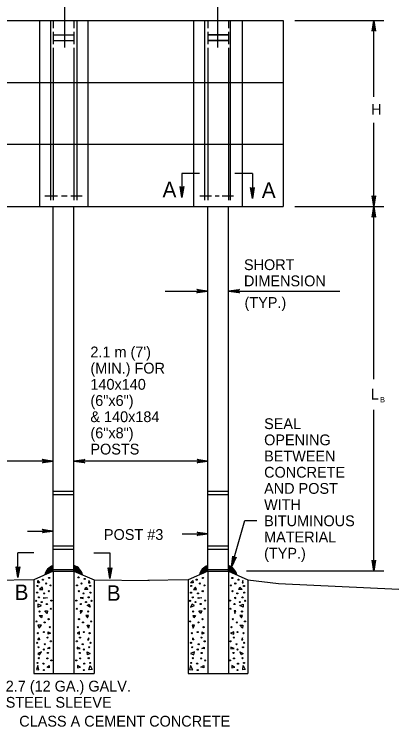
# Model space of a CAD drawing. Extents: x -1958 to 628, y -879 to 309.
# Drawn here: x 246.6 to 353.5, y 4.9 to 203 of the extents above; entities that cross this region are included whole.
import ezdxf

# ---------------------------------------------------------------- set-up
doc = ezdxf.new("R2010")
doc.units = 0
for name, color, linetype in [('2', 7, 'Continuous'), ('3', 7, 'Continuous'), ('4', 7, 'Continuous')]:
    doc.layers.add(name, color=color, linetype=linetype)

# ---------------------------------------------------------------- blocks, each defined once
blk = doc.blocks.new('RARROW')
at = {"layer": '3'}
blk.add_lwpolyline([(-0.0576, 0.0072), (-0.0555, 0.0031), (0, 0), (-0.0576, 0.0072), (-0.0606, 0.0098), (0, 0), (-0.0555, -0.0027), (-0.0575, -0.0069), (0, 0), (-0.0606, -0.0096), (-0.0575, -0.0069)], dxfattribs=at)

msp = doc.modelspace()

# ---------------------------------------------------------------- linework, layer by layer
at = {"layer": '2'}
for p, q in [((199.49, 201.26), (321.32, 201.26)), ((253.6, 201.26), (253.6, 149.52)), ((256.67, 201.26), (256.67, 151.25)), ((257.45, 201.26), (257.45, 199.13)), ((263.2, 201.26), (263.2, 199.13)), ((263.99, 201.26), (263.99, 151.25)), ((267.06, 201.26), (267.06, 149.52)), ((296.44, 201.26), (296.44, 149.52)), ((299.51, 201.26), (299.51, 151.25)), ((300.45, 201.26), (300.45, 199.13)), ((306.12, 201.26), (306.12, 199.13)), ((306.59, 201.26), (306.59, 151.25)), ((309.98, 201.26), (309.98, 149.52)), ((321.32, 201.26), (321.32, 149.52)), ((257.45, 198.03), (257.45, 194.65)), ((263.2, 198.03), (263.2, 194.65)), ((300.45, 198.03), (300.45, 194.65)), ((306.12, 198.03), (306.12, 194.65)), ((257.45, 197.24), (263.2, 197.24)), ((300.45, 197.24), (306.12, 197.24)), ((306.12, 197.24), (300.45, 197.24)), ((257.45, 195.67), (263.2, 195.67)), ((300.45, 195.67), (306.12, 195.67)), ((306.12, 195.67), (300.45, 195.67)), ((257.45, 193.62), (257.45, 151.25)), ((263.2, 193.62), (263.2, 151.25)), ((300.45, 193.62), (300.45, 151.25)), ((306.12, 193.62), (306.12, 151.25)), ((199.49, 184.01), (321.32, 184.01)), ((199.49, 166.85), (321.32, 166.85)), ((199.49, 149.52), (321.32, 149.52)), ((257.45, 48.2), (257.45, 149.52)), ((263.2, 48.2), (263.2, 149.52)), ((300.45, 48.2), (300.45, 149.52)), ((306.12, 48.2), (306.12, 149.52)), ((257.45, 70.41), (263.21, 70.41)), ((257.45, 69.47), (263.21, 69.47)), ((300.32, 70.41), (306.22, 70.41)), ((300.32, 70.41), (305.99, 70.41)), ((300.32, 69.47), (306.22, 69.47)), ((300.32, 69.47), (305.99, 69.47)), ((257.45, 55.21), (263.21, 55.21)), ((257.45, 54.27), (263.21, 54.27)), ((300.45, 55.21), (306.12, 55.21)), ((300.45, 54.27), (306.12, 54.27)), ((257.45, 48.2), (252.02, 45.76)), ((257.45, 48.68), (263.2, 48.68)), ((257.45, 48.2), (263.2, 48.2)), ((257.45, 48.2), (257.45, 19.7)), ((263.2, 48.2), (268.79, 45.76)), ((263.2, 48.2), (263.2, 19.7)), ((300.45, 48.2), (294.94, 45.76)), ((300.45, 48.68), (306.12, 48.68)), ((300.45, 48.2), (306.12, 48.2)), ((300.45, 48.2), (300.45, 19.7)), ((306.12, 48.2), (311.56, 45.76)), ((306.12, 48.2), (306.12, 19.7)), ((252.02, 45.76), (252.02, 19.7)), ((268.79, 45.76), (268.79, 19.7)), ((294.94, 45.76), (294.94, 19.7)), ((311.56, 45.76), (311.56, 19.7)), ((252.02, 19.7), (268.79, 19.7)), ((294.94, 19.7), (311.56, 19.7))]:
    msp.add_line(p, q, dxfattribs=at)
for points in [[(252.02, 45.76), (240.92, 45.6)], [(268.79, 45.76), (284.07, 45.6)], [(294.94, 45.76), (283.76, 45.6)], [(311.56, 45.76), (320.02, 44.72), (353.48, 43.14)]]:
    msp.add_lwpolyline(points, dxfattribs=at)
for points in [[(253.6, 44.9), (253.12, 44.9), (253.2, 45.6)], [(267.22, 44.9), (267.69, 44.9), (267.38, 45.6)], [(296.36, 44.9), (295.57, 44.9), (296.2, 45.6)], [(309.98, 44.9), (310.22, 44.9), (310.14, 45.6)], [(253.6, 43.08), (254.54, 43.08), (254.38, 43.71)], [(267.06, 43.08), (266.27, 43.08), (266.51, 43.71)], [(296.44, 43.08), (297.3, 43.08), (296.99, 43.71)], [(309.98, 43.08), (309.04, 43.08), (309.27, 43.71)], [(254.86, 40.56), (254.86, 40.88), (255.88, 40.72)], [(265.72, 40.56), (265.72, 40.88), (264.94, 40.72)], [(297.77, 40.56), (297.77, 40.88), (298.72, 40.72)], [(308.17, 40.56), (308.17, 40.88), (307.7, 40.72)], [(253.12, 38.99), (253.12, 38.2), (254.15, 38.67)], [(267.46, 38.99), (267.69, 38.2), (266.9, 38.67)], [(296.04, 38.99), (295.57, 38.2), (296.67, 38.67)], [(310.22, 38.99), (310.22, 38.2), (309.35, 38.67)], [(253.52, 35.84), (254.38, 35.84), (254.15, 35.21)], [(255.09, 37.18), (255.88, 37.18), (255.72, 36.39)], [(265.57, 37.18), (264.94, 37.18), (265.01, 36.39)], [(267.22, 35.84), (266.51, 35.84), (266.98, 35.21)], [(296.36, 35.84), (296.99, 35.84), (296.51, 35.21)], [(297.93, 37.18), (298.72, 37.18), (298.48, 36.39)], [(308.17, 37.18), (307.7, 37.18), (307.93, 36.39)], [(310.06, 35.84), (309.27, 35.84), (309.74, 35.21)], [(254.15, 33.16), (253.2, 33.16), (253.52, 32.3)], [(266.9, 33.16), (267.46, 33.16), (267.22, 32.3)], [(296.67, 33.16), (296.04, 33.16), (296.36, 32.3)], [(309.35, 33.16), (310.14, 33.16), (310.06, 32.3)], [(256.04, 30.64), (256.04, 31.35), (256.67, 30.96)], [(264.7, 30.64), (264.7, 31.35), (264.07, 30.96)], [(298.8, 30.64), (298.8, 31.35), (299.43, 30.96)], [(307.62, 30.64), (307.62, 31.35), (306.75, 30.96)], [(253.67, 29.07), (253.2, 29.07), (253.52, 29.62)], [(266.98, 29.07), (267.38, 29.07), (267.3, 29.62)], [(296.51, 29.07), (296.2, 29.07), (296.28, 29.62)], [(309.74, 29.07), (310.14, 29.07), (310.06, 29.62)], [(253.67, 24.97), (254.15, 25.76), (253.12, 25.29)], [(256.43, 27.02), (256.43, 26.63), (255.88, 26.7)], [(264.07, 27.02), (264.07, 26.63), (264.94, 26.7)], [(266.98, 24.97), (266.9, 25.76), (267.69, 25.29)], [(296.51, 24.97), (296.67, 25.76), (295.57, 25.29)], [(299.35, 27.02), (299.35, 26.63), (298.72, 26.7)], [(306.83, 27.02), (306.83, 26.63), (307.7, 26.7)], [(309.74, 24.97), (309.35, 25.76), (310.22, 25.29)], [(252.81, 20.88), (253.44, 20.8), (253.12, 21.98)], [(256.35, 21.98), (256.35, 21.35), (255.72, 21.51)], [(264.23, 21.98), (264.23, 21.35), (265.01, 21.51)], [(268.24, 20.88), (267.3, 20.8), (267.69, 21.98)], [(295.33, 20.88), (296.28, 20.8), (295.57, 21.98)], [(299.27, 21.98), (299.27, 21.35), (298.48, 21.51)], [(307.07, 21.98), (307.07, 21.35), (307.93, 21.51)], [(310.77, 20.88), (310.14, 20.8), (310.22, 21.98)]]:
    msp.add_lwpolyline(points, close=True, dxfattribs=at)
for centre, major_axis, start_param, end_param in [((258.64, 46.67), (-3.59, 0), 5.049782, 6.134444), ((258.64, 46.67), (-3.48, 0), 5.061257, 6.112974), ((261.99, 46.72), (3.48, 0), 0.164297, 1.213759), ((261.99, 46.72), (3.59, 0), 0.143581, 1.218869), ((261.99, 46.72), (3.35, 0), 0.193006, 1.190655), ((301.63, 46.68), (-3.59, 0), 5.048279, 6.134323), ((301.63, 46.68), (-3.48, 0), 5.058902, 6.113111), ((304.89, 46.69), (3.59, 0), 0.146911, 1.218869), ((304.89, 46.69), (3.48, 0), 0.168297, 1.204055), ((258.64, 46.67), (-3.35, 0), 5.075898, 6.083179), ((258.64, 46.67), (-3.18, 0), 5.095864, 6.041663), ((258.64, 46.67), (-3.03, 0), 5.116244, 5.998084), ((258.64, 46.67), (-2.87, 0), 5.140569, 5.94416), ((258.64, 46.67), (-2.69, 0), 5.185431, 5.865794), ((258.64, 46.67), (-2.52, 0), 5.215878, 5.780715), ((258.64, 46.67), (-2.35, 0), 5.263543, 5.680676), ((258.64, 46.67), (-2.17, 0), 5.317304, 5.495478), ((261.99, 46.72), (2.52, 0), 0.502471, 1.067308), ((261.99, 46.72), (2.69, 0), 0.391681, 1.097754), ((261.99, 46.72), (3.18, 0), 0.232926, 1.171279), ((261.99, 46.72), (3.03, 0), 0.274712, 1.150118), ((261.99, 46.72), (2.87, 0), 0.326219, 1.124043), ((261.99, 46.72), (2.35, 0), 0.60251, 1.019643), ((261.99, 46.72), (2.17, 0), 0.745101, 0.965881), ((301.63, 46.68), (-3.35, 0), 5.073435, 6.083689), ((301.63, 46.68), (-3.18, 0), 5.093253, 6.042722), ((301.63, 46.68), (-3.03, 0), 5.113478, 5.999761), ((301.63, 46.68), (-2.87, 0), 5.137615, 5.946674), ((301.63, 46.68), (-2.69, 0), 5.166915, 5.878941), ((301.63, 46.68), (-2.52, 0), 5.201449, 5.780715), ((301.63, 46.68), (-2.35, 0), 5.238657, 5.680676), ((301.63, 46.68), (-2.17, 0), 5.288522, 5.513079), ((304.89, 46.69), (2.52, 0), 0.502471, 1.067308), ((304.89, 46.69), (2.69, 0), 0.417391, 1.097754), ((304.89, 46.69), (3.35, 0), 0.197969, 1.190655), ((304.89, 46.69), (3.18, 0), 0.239305, 1.171279), ((304.89, 46.69), (3.03, 0), 0.282682, 1.150118), ((304.89, 46.69), (2.87, 0), 0.336331, 1.124043), ((304.89, 46.69), (2.35, 0), 0.60251, 1.019643), ((304.89, 46.69), (2.17, 0), 0.779924, 0.965881)]:
    msp.add_ellipse(centre, major_axis=major_axis, ratio=0.9, start_param=start_param, end_param=end_param, dxfattribs=at)
for centre, major_axis, ratio in [((254.57, 45.8), (0.154, 0), 0.99999), ((256.3, 46.28), (0.154, 0), 0.99999), ((264.47, 46.46), (-0.154, 0), 0.9), ((266.19, 46.03), (-0.154, 0), 0.9), ((297.32, 45.8), (0.154, 0), 0.99999), ((299.04, 46.28), (0.154, 0), 0.99999), ((307.22, 46.28), (-0.154, 0), 0.99999), ((308.94, 45.8), (-0.154, 0), 0.99999), ((253.05, 44.07), (0.154, 0), 0.99999), ((255.47, 44.76), (0.154, 0), 0.99999), ((256.71, 44.21), (0.154, 0), 0.99999), ((264.06, 44.21), (-0.154, 0), 0.99999), ((265.3, 44.76), (-0.154, 0), 0.99999), ((267.71, 44.07), (-0.154, 0), 0.99999), ((295.8, 44.07), (0.154, 0), 0.99999), ((298.22, 44.76), (0.154, 0), 0.99999), ((299.46, 44.21), (0.154, 0), 0.99999), ((306.81, 44.21), (-0.154, 0), 0.99999), ((308.05, 44.76), (-0.154, 0), 0.99999), ((310.46, 44.07), (-0.154, 0), 0.99999), ((252.99, 42.21), (0.154, 0), 0.99999), ((254.92, 42), (0.154, 0), 0.99999), ((256.23, 42.62), (0.154, 0), 0.99999), ((264.54, 42.62), (-0.154, 0), 0.99999), ((265.85, 42), (-0.154, 0), 0.99999), ((267.78, 42.21), (-0.154, 0), 0.99999), ((295.73, 42.21), (0.154, 0), 0.99999), ((297.67, 42), (0.154, 0), 0.99999), ((298.98, 42.62), (0.154, 0), 0.99999), ((307.29, 42.62), (-0.154, 0), 0.99999), ((308.6, 42), (-0.154, 0), 0.99999), ((310.53, 42.21), (-0.154, 0), 0.99999), ((252.71, 39.93), (0.154, 0), 0.99999), ((253.47, 40.9), (0.154, 0), 0.99999), ((254.23, 39.59), (0.154, 0), 0.99999), ((256.92, 40), (0.154, 0), 0.99999), ((263.85, 40), (-0.154, 0), 0.99999), ((266.54, 39.59), (-0.154, 0), 0.99999), ((267.3, 40.9), (-0.154, 0), 0.99999), ((268.06, 39.93), (-0.154, 0), 0.99999), ((295.46, 39.93), (0.154, 0), 0.99999), ((296.22, 40.9), (0.154, 0), 0.99999), ((296.98, 39.59), (0.154, 0), 0.99999), ((299.67, 40), (0.154, 0), 0.99999), ((306.6, 40), (-0.154, 0), 0.99999), ((309.29, 39.59), (-0.154, 0), 0.99999), ((310.05, 40.9), (-0.154, 0), 0.99999), ((310.81, 39.93), (-0.154, 0), 0.99999), ((255.67, 39.04), (0.154, 0), 0.99999), ((256.78, 37.73), (0.154, 0), 0.99999), ((263.99, 37.73), (-0.154, 0), 0.99999), ((265.09, 39.04), (-0.154, 0), 0.99999), ((298.42, 39.04), (0.154, 0), 0.99999), ((299.53, 37.73), (0.154, 0), 0.99999), ((306.74, 37.73), (-0.154, 0), 0.99999), ((307.84, 39.04), (-0.154, 0), 0.99999), ((253.61, 36.97), (0.154, 0), 0.99999), ((267.16, 36.97), (-0.154, 0), 0.99999), ((296.36, 36.97), (0.154, 0), 0.99999), ((309.91, 36.97), (-0.154, 0), 0.99999), ((252.78, 34.21), (0.154, 0), 0.99999), ((255.05, 33.93), (0.154, 0), 0.99999), ((256.16, 34.83), (0.154, 0), 0.99999), ((264.61, 34.83), (-0.154, 0), 0.99999), ((265.71, 33.93), (-0.154, 0), 0.99999), ((267.99, 34.21), (-0.154, 0), 0.99999), ((295.53, 34.21), (0.154, 0), 0.99999), ((297.8, 33.93), (0.154, 0), 0.99999), ((298.91, 34.83), (0.154, 0), 0.99999), ((307.36, 34.83), (-0.154, 0), 0.99999), ((308.46, 33.93), (-0.154, 0), 0.99999), ((310.74, 34.21), (-0.154, 0), 0.99999), ((256.5, 32.62), (0.154, 0), 0.99999), ((264.26, 32.62), (-0.154, 0), 0.99999), ((299.25, 32.62), (0.154, 0), 0.99999), ((307.01, 32.62), (-0.154, 0), 0.99999), ((253.19, 30.96), (0.154, 0), 0.99999), ((254.85, 31.24), (0.154, 0), 0.99999), ((255.88, 29.72), (0.154, 0), 0.99999), ((264.88, 29.72), (-0.154, 0), 0.99999), ((265.92, 31.24), (-0.154, 0), 0.99999), ((267.57, 30.96), (-0.154, 0), 0.99999), ((295.94, 30.96), (0.154, 0), 0.99999), ((297.6, 31.24), (0.154, 0), 0.99999), ((298.63, 29.72), (0.154, 0), 0.99999), ((307.63, 29.72), (-0.154, 0), 0.99999), ((308.67, 31.24), (-0.154, 0), 0.99999), ((310.32, 30.96), (-0.154, 0), 0.99999), ((252.99, 28.27), (0.154, 0), 0.99999), ((255.12, 27.86), (0.154, 0), 0.99999), ((256.78, 28.69), (0.154, 0), 0.99999), ((263.99, 28.69), (-0.154, 0), 0.99999), ((265.64, 27.86), (-0.154, 0), 0.99999), ((267.78, 28.27), (-0.154, 0), 0.99999), ((295.73, 28.27), (0.154, 0), 0.99999), ((297.87, 27.86), (0.154, 0), 0.99999), ((299.53, 28.69), (0.154, 0), 0.99999), ((306.74, 28.69), (-0.154, 0), 0.99999), ((308.39, 27.86), (-0.154, 0), 0.99999), ((310.53, 28.27), (-0.154, 0), 0.99999), ((253.33, 27.03), (0.154, 0), 0.99999), ((254.85, 26.41), (0.154, 0), 0.99999), ((265.92, 26.41), (-0.154, 0), 0.99999), ((267.44, 27.03), (-0.154, 0), 0.99999), ((296.08, 27.03), (0.154, 0), 0.99999), ((297.6, 26.41), (0.154, 0), 0.99999), ((308.67, 26.41), (-0.154, 0), 0.99999), ((310.18, 27.03), (-0.154, 0), 0.99999), ((253.47, 23.99), (0.154, 0), 0.99999), ((255.81, 23.93), (0.154, 0), 0.99999), ((255.95, 25.44), (0.154, 0), 0.99999), ((264.82, 25.44), (-0.154, 0), 0.99999), ((264.95, 23.93), (-0.154, 0), 0.99999), ((267.3, 23.99), (-0.154, 0), 0.99999), ((296.22, 23.99), (0.154, 0), 0.99999), ((298.56, 23.93), (0.154, 0), 0.99999), ((298.7, 25.44), (0.154, 0), 0.99999), ((307.56, 25.44), (-0.154, 0), 0.99999), ((307.7, 23.93), (-0.154, 0), 0.99999), ((310.05, 23.99), (-0.154, 0), 0.99999), ((253.05, 22.68), (0.154, 0), 0.99999), ((254.71, 22.48), (0.154, 0), 0.99999), ((256.92, 23.37), (0.154, 0), 0.99999), ((263.85, 23.37), (-0.154, 0), 0.99999), ((266.06, 22.48), (-0.154, 0), 0.99999), ((267.71, 22.68), (-0.154, 0), 0.99999), ((295.8, 22.68), (0.154, 0), 0.99999), ((297.46, 22.48), (0.154, 0), 0.99999), ((299.67, 23.37), (0.154, 0), 0.99999), ((306.6, 23.37), (-0.154, 0), 0.99999), ((308.81, 22.48), (-0.154, 0), 0.99999), ((310.46, 22.68), (-0.154, 0), 0.99999), ((254.85, 20.68), (0.154, 0), 0.99999), ((265.92, 20.68), (-0.154, 0), 0.99999), ((297.6, 20.68), (0.154, 0), 0.99999), ((308.67, 20.68), (-0.154, 0), 0.99999)]:
    msp.add_ellipse(centre, major_axis=major_axis, ratio=ratio, dxfattribs=at)
at = {"layer": '3'}
for p, q in [((260.53, 209.77), (260.53, 193.7)), ((303.13, 209.77), (303.13, 193.7)), ((324.63, 201.26), (349.31, 201.26)), ((346.55, 180.01), (346.55, 201.26)), ((346.55, 149.52), (346.55, 172.75)), ((293.2, 158.67), (293.2, 152.07)), ((298.08, 158.67), (293.2, 158.67)), ((312.81, 158.67), (307.93, 158.67)), ((312.81, 158.67), (312.81, 151.77)), ((258.63, 152.37), (255.12, 152.37)), ((261.32, 152.37), (259.76, 152.37)), ((265.51, 152.37), (262.32, 152.37)), ((301.47, 152.37), (298.15, 152.37)), ((303.6, 152.37), (302.41, 152.37)), ((307.53, 152.37), (304.42, 152.37)), ((324.63, 149.52), (349.31, 149.52)), ((346.55, 101.57), (346.55, 149.52)), ((288.54, 126), (300.38, 126)), ((306.2, 126), (337.14, 126)), ((346.55, 48.2), (346.55, 93.04)), ((257.45, 78.76), (220.6, 78.76)), ((300.45, 78.76), (263.2, 78.76)), ((250.26, 59.33), (257.45, 59.33)), ((293.29, 58.54), (300.45, 58.54)), ((247.61, 46.4), (247.61, 53.28)), ((252.02, 53.24), (247.61, 53.24)), ((268.72, 53.24), (273.2, 53.24)), ((273.2, 53.24), (273.2, 46.12)), ((349.31, 48.2), (311.16, 48.2))]:
    msp.add_line(p, q, dxfattribs=at)
msp.add_lwpolyline([(307.01, 49.29), (310.68, 62.26), (314.04, 62.26)], dxfattribs=at)

# ---------------------------------------------------------------- block references
at = {"layer": '2'}
for p, xscale, yscale, rotation in [((346.55, 201.26), 49.50530586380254, 51.54709073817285, 89.99999999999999), ((293.2, 152.07), 49.50530586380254, 51.54709073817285, -90.00000000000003), ((312.81, 151.77), 49.50530586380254, 51.54709073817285, -90.00000000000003), ((346.55, 149.52), 49.50530586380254, 51.54709073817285, -90.00000000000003), ((346.55, 149.52), 49.50530586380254, 51.54709073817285, 89.99999999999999), ((306.2, 126), 49.50530586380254, 51.54709073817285, 180), ((263.2, 78.76), 49.50530586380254, 51.54709073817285, 180), ((307.01, 49.29), 49.50530586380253, 51.547090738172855, -105.57754519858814), ((346.55, 48.2), 49.50530586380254, 51.54709073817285, -90.00000000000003), ((247.61, 46.4), 49.50530586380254, 51.54709073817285, -90.00000000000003), ((273.2, 46.12), 49.50530586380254, 51.54709073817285, -90.00000000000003)]:
    msp.add_blockref('RARROW', p, dxfattribs=dict(at, xscale=xscale, yscale=yscale, rotation=rotation))
at = {"layer": '2', "xscale": 49.50530586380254, "yscale": 51.54709073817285}
for p in [(300.38, 126), (257.45, 78.76), (300.45, 78.76), (257.45, 59.33), (300.45, 58.54)]:
    msp.add_blockref('RARROW', p, dxfattribs=at)

# ---------------------------------------------------------------- texts
at = {"layer": '2'}
for s, p in [("2.1 m (7')", (267.78, 107.6)), ('(MIN.) FOR', (267.78, 103.1)), ('140x140 ', (267.78, 98.6)), ('(6"x6") ', (267.78, 94.1)), ('& 140x184', (267.78, 89.6)), ('(6"x8") ', (267.78, 85.1)), ('POSTS', (267.78, 80.6))]:
    msp.add_text(s, height=3, dxfattribs=at).set_placement(p)
at = {"layer": '3'}
for s, height, p in [('H', 3, (345.79, 175.02)), ('A', 4.3, (287.83, 152.08)), ('A', 4.3, (315.42, 151.92)), ('SHORT', 3, (310.46, 131.85)), ('DIMENSION', 3, (310.46, 127.35)), ('(TYP.)', 3, (310.62, 121.35)), ('L', 3, (345.7, 95.86)), ('SEAL', 3, (316.06, 87.67)), ('OPENING ', 3, (316.06, 83.17)), ('BETWEEN', 3, (316.06, 78.67)), ('CONCRETE', 3, (316.06, 74.17)), ('AND POST', 3, (316.06, 69.67)), ('WITH', 3, (316.06, 65.17)), ('BITUMINOUS ', 3, (316.06, 60.67)), ('POST #3', 3, (271.54, 56.86)), ('MATERIAL', 3, (316.06, 56.17)), ('(TYP.)', 3, (316.06, 51.67)), ('B', 4.3, (246.72, 40.17)), ('B', 4.3, (272.34, 39.94)), ('2.7 (12 GA.) GALV.', 3, (244.24, 14.73)), ('STEEL SLEEVE', 3, (244.24, 10.23)), ('CLASS A CEMENT CONCRETE ', 3, (248, 4.98))]:
    msp.add_text(s, height=height, dxfattribs=at).set_placement(p)
at = {"layer": '4'}
msp.add_text('B', height=1.5, dxfattribs=at).set_placement((348.27, 95.09))

doc.saveas('drawing.dxf')
